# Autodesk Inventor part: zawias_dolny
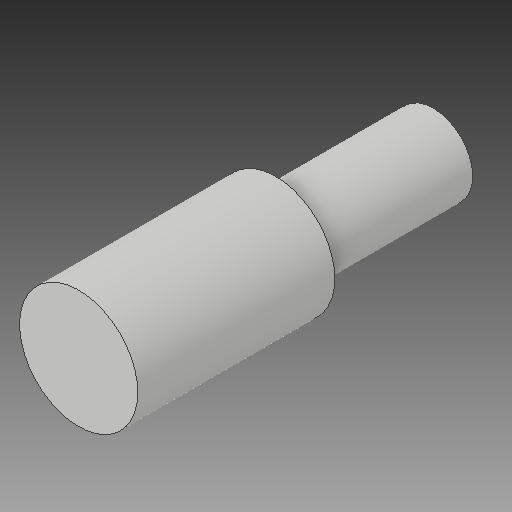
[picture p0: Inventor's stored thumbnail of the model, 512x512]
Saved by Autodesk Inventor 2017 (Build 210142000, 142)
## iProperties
Created: 2020-09
Part Number: zawias_dolny
Material: Generic
Document SubType Name: Modeling
Designer: WindowsX
Density: 1 g/cm^3
Appearance: Default
Mass: 47.9093 g
Surface Area: 86.3938 cm^2
Volume: 47.9093 cm^3
Author: WindowsX
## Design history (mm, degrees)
sketch "Szkic1"
  geometry: C1 r 15 at (0, 0); 1 further point
  constraints: 1 centre point, 1 coincident
  dimensions: "d1" = 30 diameter of C1
extrude "Wyciągnięcie proste1" new body sketch "Szkic1" distance "d2" = 50; taper "d3" = 0 deg
sketch "Szkic2"
  geometry: C1 r 10 at (0, 0); 1 further point
  constraints: 1 centre point, 1 coincident
  dimensions: "d4" = 20 diameter of C1
extrude "Wyciągnięcie proste2" join sketch "Szkic2" distance "d5" = 40; taper "d6" = 0 deg
node "Bryła1"
